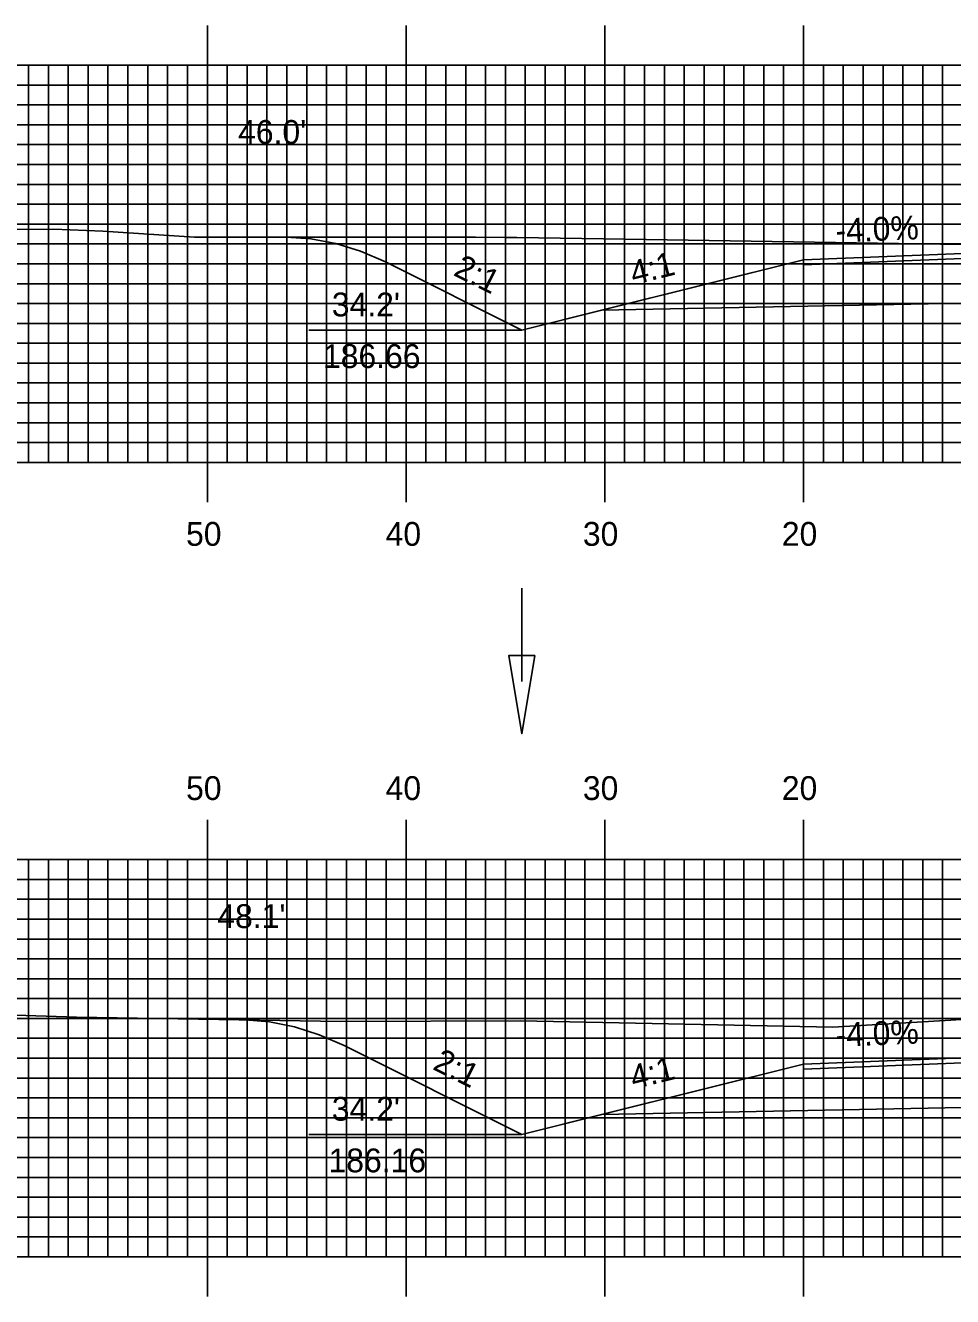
# Model space of a CAD drawing. Extents: x 1798388 to 1798731, y 442591 to 442811.
# Drawn here: x 1798494.3 to 1798541, y 442696.7 to 442760.7 of the extents above; entities that cross this region are included whole.
import ezdxf

# ---------------------------------------------------------------- set-up
doc = ezdxf.new("R2010")
doc.units = 0
for name, color, linetype in [('ANNOTATION', 7, 'Continuous'), ('D_Drainage_Ditch_Line', 7, 'Continuous'), ('D_Roadway_Centerline', 7, 'Continuous'), ('D_Roadway_Edge_Shoulder', 7, 'Continuous'), ('D_Roadway_SlopeLines', 7, 'Continuous'), ('D_Roadway_SubGrade', 7, 'Continuous'), ('D_Text_Standard', 7, 'Continuous'), ('H_V ANNOTATION', 7, 'Continuous'), ('MAJOR', 7, 'Continuous'), ('MINOR', 7, 'Continuous'), ('PDRAIN', 7, 'Continuous'), ('S_Roadway_Centerline', 7, 'Continuous')]:
    doc.layers.add(name, color=color, linetype=linetype)

msp = doc.modelspace()

# ---------------------------------------------------------------- linework, layer by layer
at = {"layer": 'D_Drainage_Ditch_Line'}
msp.add_line((1798519.297, 442727.626), (1798519.297, 442732.325), dxfattribs=at)
msp.add_lwpolyline([(1798519.953, 442728.939), (1798518.641, 442728.939), (1798519.297, 442725.002)], close=True, dxfattribs=at)
at = {"layer": 'D_Roadway_Centerline'}
for points in [[(1798507.432, 442750.009), (1798508.682, 442749.93), (1798509.932, 442749.696), (1798511.182, 442749.305), (1798512.432, 442748.758), (1798519.297, 442745.325), (1798523.297, 442746.325), (1798533.471, 442748.869), (1798541.471, 442749.189), (1798553.471, 442748.949), (1798565.471, 442748.709), (1798573.471, 442748.389), (1798583.645, 442745.845), (1798587.645, 442744.845), (1798594.216, 442748.131), (1798595.466, 442748.676), (1798596.716, 442749.061), (1798597.966, 442749.287), (1798599.216, 442749.352)], [(1798505.35, 442710.592), (1798506.6, 442710.495), (1798507.85, 442710.247), (1798509.1, 442709.848), (1798510.35, 442709.299), (1798519.297, 442704.825), (1798523.297, 442705.825), (1798533.471, 442708.369), (1798541.471, 442708.689), (1798553.471, 442708.449), (1798565.471, 442708.209), (1798573.471, 442707.889), (1798583.645, 442705.345), (1798587.645, 442704.345), (1798594.222, 442707.634), (1798595.472, 442708.176), (1798596.722, 442708.553), (1798597.972, 442708.765), (1798599.222, 442708.811)]]:
    msp.add_lwpolyline(points, dxfattribs=at)
at = {"layer": 'D_Roadway_Edge_Shoulder'}
for points in [[(1798541.471, 442749.189), (1798533.471, 442748.869), (1798533.471, 442748.619), (1798541.471, 442748.939)], [(1798541.471, 442708.689), (1798533.471, 442708.369), (1798533.471, 442708.119), (1798541.471, 442708.439)]]:
    msp.add_lwpolyline(points, close=True, dxfattribs=at)
at = {"layer": 'D_Roadway_SlopeLines'}
for points in [[(1798519.297, 442745.325), (1798512.432, 442748.758), (1798511.182, 442749.305), (1798509.932, 442749.696), (1798508.682, 442749.93), (1798507.432, 442750.009)], [(1798533.471, 442748.869), (1798519.297, 442745.325)], [(1798519.297, 442704.825), (1798510.35, 442709.299), (1798509.1, 442709.848), (1798507.85, 442710.247), (1798506.6, 442710.495), (1798505.35, 442710.592)], [(1798533.471, 442708.369), (1798519.297, 442704.825)]]:
    msp.add_lwpolyline(points, dxfattribs=at)
at = {"layer": 'D_Roadway_SubGrade'}
for points in [[(1798541.471, 442746.689), (1798523.297, 442746.325), (1798533.471, 442748.869), (1798533.471, 442748.619), (1798541.471, 442748.939), (1798553.471, 442748.699), (1798565.471, 442748.459), (1798573.471, 442748.139), (1798573.471, 442748.389), (1798583.645, 442745.845), (1798565.471, 442746.209), (1798553.471, 442746.449)], [(1798541.471, 442706.189), (1798523.297, 442705.825), (1798533.471, 442708.369), (1798533.471, 442708.119), (1798541.471, 442708.439), (1798553.471, 442708.199), (1798565.471, 442707.959), (1798573.471, 442707.639), (1798573.471, 442707.889), (1798583.645, 442705.345), (1798565.471, 442705.709), (1798553.471, 442705.949)]]:
    msp.add_lwpolyline(points, close=True, dxfattribs=at)
at = {"layer": 'MAJOR'}
for p, q in [((1798503.471, 442760.669), (1798503.471, 442758.665)), ((1798513.471, 442760.669), (1798513.471, 442758.665)), ((1798523.471, 442760.669), (1798523.471, 442758.665)), ((1798533.471, 442760.669), (1798533.471, 442758.665)), ((1798413.471, 442758.665), (1798693.471, 442758.665)), ((1798413.471, 442758.665), (1798693.471, 442758.665)), ((1798503.471, 442738.665), (1798503.471, 442758.665)), ((1798513.471, 442738.665), (1798513.471, 442758.665)), ((1798523.471, 442738.665), (1798523.471, 442758.665)), ((1798533.471, 442738.665), (1798533.471, 442758.665)), ((1798413.471, 442753.665), (1798693.471, 442753.665)), ((1798413.471, 442748.665), (1798693.471, 442748.665)), ((1798413.471, 442743.665), (1798693.471, 442743.665)), ((1798413.471, 442738.665), (1798693.471, 442738.665)), ((1798413.471, 442738.665), (1798693.471, 442738.665)), ((1798503.471, 442736.661), (1798503.471, 442738.665)), ((1798513.471, 442736.661), (1798513.471, 442738.665)), ((1798523.471, 442736.661), (1798523.471, 442738.665)), ((1798533.471, 442736.661), (1798533.471, 442738.665)), ((1798503.471, 442720.669), (1798503.471, 442718.665)), ((1798513.471, 442720.669), (1798513.471, 442718.665)), ((1798523.471, 442720.669), (1798523.471, 442718.665)), ((1798533.471, 442720.669), (1798533.471, 442718.665)), ((1798413.471, 442718.665), (1798693.471, 442718.665)), ((1798413.471, 442718.665), (1798693.471, 442718.665)), ((1798503.471, 442698.665), (1798503.471, 442718.665)), ((1798513.471, 442698.665), (1798513.471, 442718.665)), ((1798523.471, 442698.665), (1798523.471, 442718.665)), ((1798533.471, 442698.665), (1798533.471, 442718.665)), ((1798413.471, 442713.665), (1798693.471, 442713.665)), ((1798413.471, 442708.665), (1798693.471, 442708.665)), ((1798413.471, 442703.665), (1798693.471, 442703.665)), ((1798413.471, 442698.665), (1798693.471, 442698.665)), ((1798413.471, 442698.665), (1798693.471, 442698.665)), ((1798503.471, 442696.661), (1798503.471, 442698.665)), ((1798513.471, 442696.661), (1798513.471, 442698.665)), ((1798523.471, 442696.661), (1798523.471, 442698.665)), ((1798533.471, 442696.661), (1798533.471, 442698.665))]:
    msp.add_line(p, q, dxfattribs=at)
at = {"layer": 'MINOR'}
for p, q in [((1798494.471, 442738.665), (1798494.471, 442758.665)), ((1798495.471, 442738.665), (1798495.471, 442758.665)), ((1798496.471, 442738.665), (1798496.471, 442758.665)), ((1798497.471, 442738.665), (1798497.471, 442758.665)), ((1798498.471, 442738.665), (1798498.471, 442758.665)), ((1798499.471, 442738.665), (1798499.471, 442758.665)), ((1798500.471, 442738.665), (1798500.471, 442758.665)), ((1798501.471, 442738.665), (1798501.471, 442758.665)), ((1798502.471, 442738.665), (1798502.471, 442758.665)), ((1798504.471, 442738.665), (1798504.471, 442758.665)), ((1798505.471, 442738.665), (1798505.471, 442758.665)), ((1798506.471, 442738.665), (1798506.471, 442758.665)), ((1798507.471, 442738.665), (1798507.471, 442758.665)), ((1798508.471, 442738.665), (1798508.471, 442758.665)), ((1798509.471, 442738.665), (1798509.471, 442758.665)), ((1798510.471, 442738.665), (1798510.471, 442758.665)), ((1798511.471, 442738.665), (1798511.471, 442758.665)), ((1798512.471, 442738.665), (1798512.471, 442758.665)), ((1798514.471, 442738.665), (1798514.471, 442758.665)), ((1798515.471, 442738.665), (1798515.471, 442758.665)), ((1798516.471, 442738.665), (1798516.471, 442758.665)), ((1798517.471, 442738.665), (1798517.471, 442758.665)), ((1798518.471, 442738.665), (1798518.471, 442758.665)), ((1798519.471, 442738.665), (1798519.471, 442758.665)), ((1798520.471, 442738.665), (1798520.471, 442758.665)), ((1798521.471, 442738.665), (1798521.471, 442758.665)), ((1798522.471, 442738.665), (1798522.471, 442758.665)), ((1798524.471, 442738.665), (1798524.471, 442758.665)), ((1798525.471, 442738.665), (1798525.471, 442758.665)), ((1798526.471, 442738.665), (1798526.471, 442758.665)), ((1798527.471, 442738.665), (1798527.471, 442758.665)), ((1798528.471, 442738.665), (1798528.471, 442758.665)), ((1798529.471, 442738.665), (1798529.471, 442758.665)), ((1798530.471, 442738.665), (1798530.471, 442758.665)), ((1798531.471, 442738.665), (1798531.471, 442758.665)), ((1798532.471, 442738.665), (1798532.471, 442758.665)), ((1798534.471, 442738.665), (1798534.471, 442758.665)), ((1798535.471, 442738.665), (1798535.471, 442758.665)), ((1798536.471, 442738.665), (1798536.471, 442758.665)), ((1798537.471, 442738.665), (1798537.471, 442758.665)), ((1798538.471, 442738.665), (1798538.471, 442758.665)), ((1798539.471, 442738.665), (1798539.471, 442758.665)), ((1798540.471, 442738.665), (1798540.471, 442758.665)), ((1798413.471, 442757.665), (1798693.471, 442757.665)), ((1798413.471, 442756.665), (1798693.471, 442756.665)), ((1798413.471, 442755.665), (1798693.471, 442755.665)), ((1798413.471, 442754.665), (1798693.471, 442754.665)), ((1798413.471, 442752.665), (1798693.471, 442752.665)), ((1798413.471, 442751.665), (1798693.471, 442751.665)), ((1798413.471, 442750.665), (1798693.471, 442750.665)), ((1798413.471, 442749.665), (1798693.471, 442749.665)), ((1798413.471, 442747.665), (1798693.471, 442747.665)), ((1798413.471, 442746.665), (1798693.471, 442746.665)), ((1798413.471, 442745.665), (1798693.471, 442745.665)), ((1798413.471, 442744.665), (1798693.471, 442744.665)), ((1798413.471, 442742.665), (1798693.471, 442742.665)), ((1798413.471, 442741.665), (1798693.471, 442741.665)), ((1798413.471, 442740.665), (1798693.471, 442740.665)), ((1798413.471, 442739.665), (1798693.471, 442739.665)), ((1798494.471, 442698.665), (1798494.471, 442718.665)), ((1798495.471, 442698.665), (1798495.471, 442718.665)), ((1798496.471, 442698.665), (1798496.471, 442718.665)), ((1798497.471, 442698.665), (1798497.471, 442718.665)), ((1798498.471, 442698.665), (1798498.471, 442718.665)), ((1798499.471, 442698.665), (1798499.471, 442718.665)), ((1798500.471, 442698.665), (1798500.471, 442718.665)), ((1798501.471, 442698.665), (1798501.471, 442718.665)), ((1798502.471, 442698.665), (1798502.471, 442718.665)), ((1798504.471, 442698.665), (1798504.471, 442718.665)), ((1798505.471, 442698.665), (1798505.471, 442718.665)), ((1798506.471, 442698.665), (1798506.471, 442718.665)), ((1798507.471, 442698.665), (1798507.471, 442718.665)), ((1798508.471, 442698.665), (1798508.471, 442718.665)), ((1798509.471, 442698.665), (1798509.471, 442718.665)), ((1798510.471, 442698.665), (1798510.471, 442718.665)), ((1798511.471, 442698.665), (1798511.471, 442718.665)), ((1798512.471, 442698.665), (1798512.471, 442718.665)), ((1798514.471, 442698.665), (1798514.471, 442718.665)), ((1798515.471, 442698.665), (1798515.471, 442718.665)), ((1798516.471, 442698.665), (1798516.471, 442718.665)), ((1798517.471, 442698.665), (1798517.471, 442718.665)), ((1798518.471, 442698.665), (1798518.471, 442718.665)), ((1798519.471, 442698.665), (1798519.471, 442718.665)), ((1798520.471, 442698.665), (1798520.471, 442718.665)), ((1798521.471, 442698.665), (1798521.471, 442718.665)), ((1798522.471, 442698.665), (1798522.471, 442718.665)), ((1798524.471, 442698.665), (1798524.471, 442718.665)), ((1798525.471, 442698.665), (1798525.471, 442718.665)), ((1798526.471, 442698.665), (1798526.471, 442718.665)), ((1798527.471, 442698.665), (1798527.471, 442718.665)), ((1798528.471, 442698.665), (1798528.471, 442718.665)), ((1798529.471, 442698.665), (1798529.471, 442718.665)), ((1798530.471, 442698.665), (1798530.471, 442718.665)), ((1798531.471, 442698.665), (1798531.471, 442718.665)), ((1798532.471, 442698.665), (1798532.471, 442718.665)), ((1798534.471, 442698.665), (1798534.471, 442718.665)), ((1798535.471, 442698.665), (1798535.471, 442718.665)), ((1798536.471, 442698.665), (1798536.471, 442718.665)), ((1798537.471, 442698.665), (1798537.471, 442718.665)), ((1798538.471, 442698.665), (1798538.471, 442718.665)), ((1798539.471, 442698.665), (1798539.471, 442718.665)), ((1798540.471, 442698.665), (1798540.471, 442718.665)), ((1798413.471, 442717.665), (1798693.471, 442717.665)), ((1798413.471, 442716.665), (1798693.471, 442716.665)), ((1798413.471, 442715.665), (1798693.471, 442715.665)), ((1798413.471, 442714.665), (1798693.471, 442714.665)), ((1798413.471, 442712.665), (1798693.471, 442712.665)), ((1798413.471, 442711.665), (1798693.471, 442711.665)), ((1798413.471, 442710.665), (1798693.471, 442710.665)), ((1798413.471, 442709.665), (1798693.471, 442709.665)), ((1798413.471, 442707.665), (1798693.471, 442707.665)), ((1798413.471, 442706.665), (1798693.471, 442706.665)), ((1798413.471, 442705.665), (1798693.471, 442705.665)), ((1798413.471, 442704.665), (1798693.471, 442704.665)), ((1798413.471, 442702.665), (1798693.471, 442702.665)), ((1798413.471, 442701.665), (1798693.471, 442701.665)), ((1798413.471, 442700.665), (1798693.471, 442700.665)), ((1798413.471, 442699.665), (1798693.471, 442699.665))]:
    msp.add_line(p, q, dxfattribs=at)
at = {"layer": 'PDRAIN'}
for p, q in [((1798508.574, 442745.325), (1798519.297, 442745.325)), ((1798508.574, 442704.825), (1798519.297, 442704.825))]:
    msp.add_line(p, q, dxfattribs=at)
at = {"layer": 'S_Roadway_Centerline'}
for points in [[(1798474.572, 442750.35), (1798495.745, 442750.413), (1798498.22, 442750.306), (1798502.827, 442750.011), (1798516.971, 442750.005), (1798518.506, 442749.989), (1798519.037, 442749.991), (1798524.492, 442749.906), (1798540.357, 442749.649), (1798541.944, 442749.661), (1798561.083, 442749.923), (1798566.412, 442749.934), (1798576.086, 442749.745), (1798585.386, 442749.59), (1798588.692, 442749.454), (1798592.089, 442749.422), (1798598.752, 442749.363), (1798605.74, 442749.203)], [(1798491.776, 442710.895), (1798496.884, 442710.737), (1798510.184, 442710.509), (1798519.231, 442710.544), (1798534.939, 442710.23), (1798540.89, 442710.575), (1798549.829, 442711.165), (1798560.753, 442709.983), (1798562.71, 442709.733), (1798584.609, 442709.231), (1798584.906, 442709.222), (1798586.136, 442709.189), (1798605.514, 442708.63)]]:
    msp.add_lwpolyline(points, dxfattribs=at)

# ---------------------------------------------------------------- texts
at = {"layer": 'ANNOTATION'}
for s, rotation, p in [('-4.0%', 2.29061, (1798535.103, 442749.736)), ('4:1', 14.03624, (1798524.919, 442747.593)), ('2:1', 333.43495, (1798515.798, 442748.111)), ('-4.0%', 2.29061, (1798535.103, 442709.236)), ('2:1', 333.43495, (1798514.757, 442708.131)), ('4:1', 14.03624, (1798524.919, 442707.093))]:
    msp.add_text(s, height=1.2, rotation=rotation, dxfattribs=at).set_placement(p)
for s, p in [("34.2'", (1798509.735, 442746.017)), ('186.66', (1798509.291, 442743.417)), ("34.2'", (1798509.735, 442705.517)), ('186.16', (1798509.569, 442702.917))]:
    msp.add_text(s, height=1.2, dxfattribs=at).set_placement(p)
at = {"layer": 'D_Text_Standard'}
for s, p in [("46.0'", (1798505.019, 442754.704)), ("48.1'", (1798503.974, 442715.218))]:
    msp.add_text(s, height=1.2, dxfattribs=at).set_placement(p)
at = {"layer": 'H_V ANNOTATION'}
for s, p in [('50', (1798502.4, 442734.465)), ('40', (1798512.443, 442734.465)), ('30', (1798522.368, 442734.465)), ('20', (1798532.379, 442734.465)), ('50', (1798502.4, 442721.665)), ('40', (1798512.443, 442721.665)), ('30', (1798522.368, 442721.665)), ('20', (1798532.379, 442721.665))]:
    msp.add_text(s, height=1.2, dxfattribs=at).set_placement(p)

doc.saveas('drawing.dxf')
